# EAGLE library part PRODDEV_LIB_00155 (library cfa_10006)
MICROSD SOCKET, CONN EJECT MICROSD PUSH-PUSH SMD
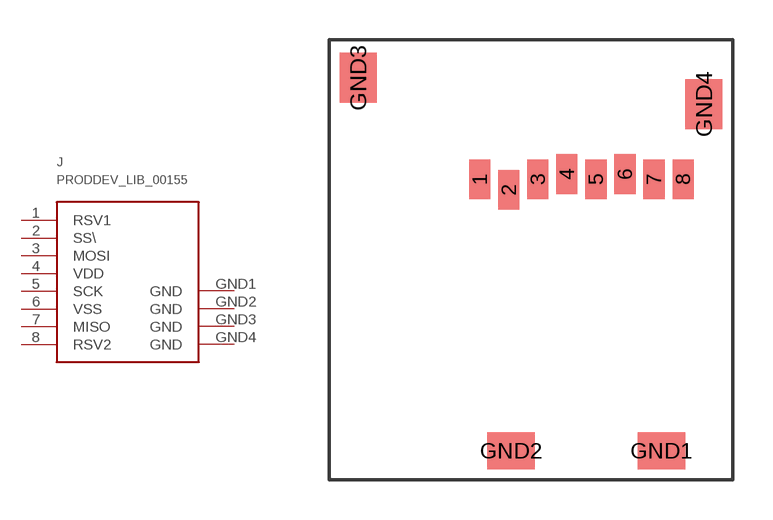
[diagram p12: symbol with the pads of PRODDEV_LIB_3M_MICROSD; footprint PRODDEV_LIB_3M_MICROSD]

Designator prefix J

## PRODDEV_LIB_00155  [PRODDEV_LIB_3M_MICROSD]
1  RSV1
2  SS\  in
3  MOSI  in
4  VDD  pwr
5  SCK  in
6  VSS  pwr
7  MISO  out
8  RSV2
GND1  GND  pwr
GND2  GND  pwr
GND3  GND  pwr
GND4  GND  pwr

## Footprint PRODDEV_LIB_3M_MICROSD (pad centres in mm)
PCB Libraries Packages
smd 0.8 x 1.5: 1 -6.89,10.3; 2 -5.79,9.9; 3 -4.69,10.3; 4 -3.59,10.5; 5 -2.49,10.3; 6 -1.39,10.5; 7 -0.29,10.3; 8 0.81,10.3
smd 1.8 x 1.4: GND1 0,0; GND2 -5.7,0
smd 1.4 x 1.9: GND3 -11.5,14.15; GND4 1.6,13.15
